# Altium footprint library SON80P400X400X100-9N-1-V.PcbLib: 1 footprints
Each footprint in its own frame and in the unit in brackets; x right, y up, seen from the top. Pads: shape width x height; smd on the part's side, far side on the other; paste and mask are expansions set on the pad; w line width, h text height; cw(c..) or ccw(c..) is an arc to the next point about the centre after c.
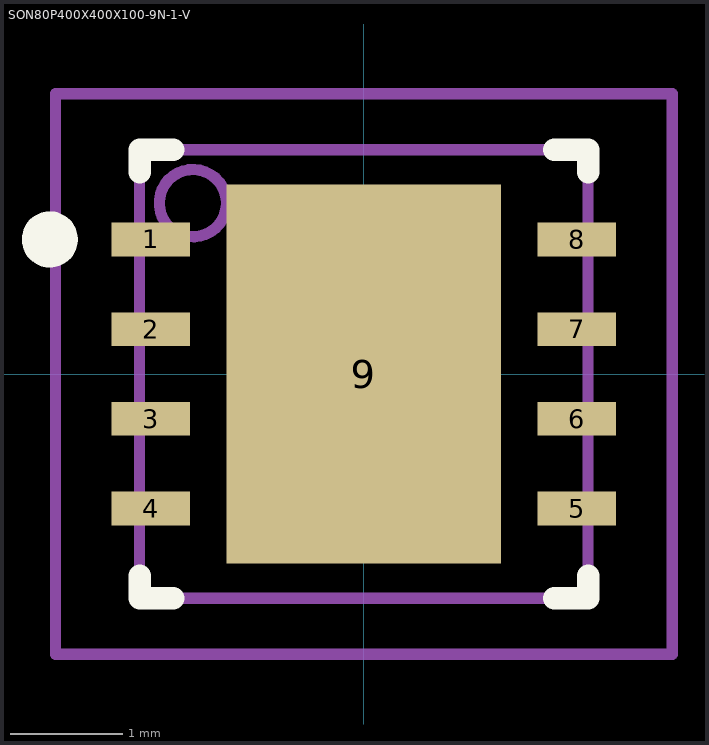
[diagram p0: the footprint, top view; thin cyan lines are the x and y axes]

## SON80P400X400X100-9N-1-V [mm] "SON,0.80mm,pitch;8 pin,4.00mm W X 4.00mm L X 1.00mm H body (w/thermal tab)"
height 1
pads (9):
  rect 0.7x0.3 smd paste+0 mask+0: 1(-1.9,1.2) 2(-1.9,0.4) 3(-1.9,-0.4) 4(-1.9,-1.2) 5(1.9,-1.2) 6(1.9,-0.4) 7(1.9,0.4) 8(1.9,1.2)
  rect 2.45x3.38 smd paste-1.69 mask+0: 9(0,0)
Top Overlay:
  circle w0.25: c-2.8,1.2 r0.125
  lines w0.2: -2,-1.8 -2,-2 -1.7,-2 ; -2,1.8 -2,2 -1.7,2 ; 1.7,-2 2,-2 2,-1.8 ; 1.7,2 2,2 2,1.8
Top Paste:
  region: 1,1.45 0.1,1.45 0.1,0.1 1,0.1
  region: -1,-1.45 -0.1,-1.45 -0.1,-0.1 -1,-0.1
  region: 1,-1.45 0.1,-1.45 0.1,-0.1 1,-0.1
  region: -1,1.45 -0.1,1.45 -0.1,0.1 -1,0.1
M3 (ASY_Text_Top):
  text ".DESIGNATOR" at 0,0 h1.2
M13 (CMP_Body_OTL_Top):
  circle w0.1: c-1.524,1.524 r0.3
  lines w0.1: -2,-2 2,-2 2,2 -2,2 -2,-2
M15 (CMP_Courtyard_Top):
  lines w0.1: -0.5,0 0.5,0 ; 0,-0.5 0,0.5 ; -2.75,-2.5 2.75,-2.5 2.75,2.5 -2.75,2.5 -2.75,-2.5
3D body "PG-VDSON-8-4.STEP": height 1, standoff 0, extent -2,-2 2,2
